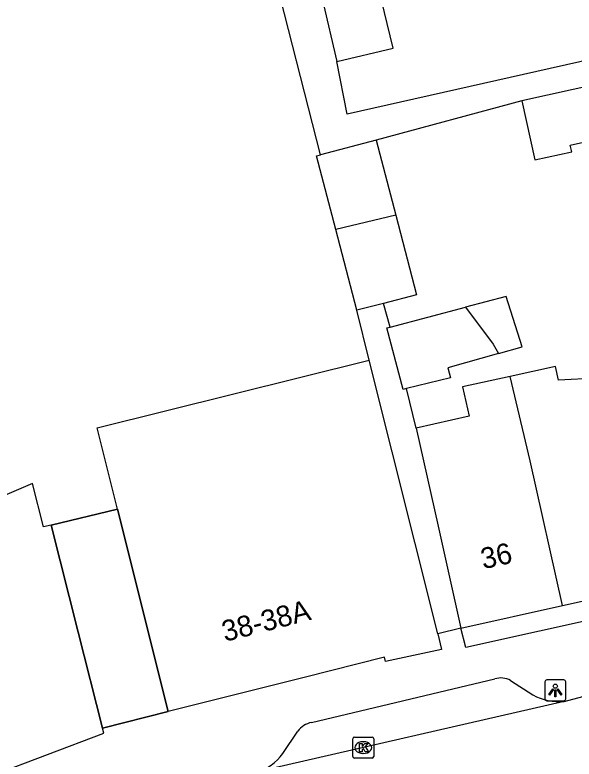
# Model space of a CAD drawing. Extents: x 160861 to 161308, y 384024 to 384878.
# Drawn here: x 160958.47 to 160985.24, y 384696.73 to 384732.38 of the extents above; entities that cross this region are included whole.
import ezdxf

# ---------------------------------------------------------------- set-up
doc = ezdxf.new("R2010")
doc.units = 0
for name, color, linetype in [('IMGEO_Kolk', 7, 'Continuous'), ('IMGEO_Lichtpunt', 7, 'Continuous'), ('IMGEO_Pand', 7, 'Continuous'), ('IMGEO_Pand_nummerreeks', 7, 'Continuous'), ('IMGEO_Pand_overbouw', 7, 'Continuous'), ('IMGEO_Rijbaan_lokaal_open', 7, 'Continuous'), ('IMGEO_Voetpad_open', 7, 'Continuous')]:
    doc.layers.add(name, color=color, linetype=linetype)

msp = doc.modelspace()

# ---------------------------------------------------------------- linework, layer by layer
at = {"layer": 'IMGEO_Kolk'}
for p, q in [((160974.647, 384696.86), (160974.647, 384697.712)), ((160974.722, 384697.786), (160975.574, 384697.786)), ((160975.648, 384697.712), (160975.648, 384696.86)), ((160975.135, 384697.566), (160975.16, 384697.566)), ((160975.158, 384697.006), (160975.133, 384697.006)), ((160975.574, 384696.786), (160974.722, 384696.786))]:
    msp.add_line(p, q, dxfattribs=at)
for points in [[(160974.647, 384696.86), (160974.647, 384697.712)], [(160974.722, 384697.786), (160975.574, 384697.786)], [(160975.648, 384697.712), (160975.648, 384696.86)], [(160974.968, 384697.486), (160975.091, 384697.486), (160975.091, 384697.335), (160975.221, 384697.486), (160975.385, 384697.486), (160975.239, 384697.335), (160975.392, 384697.086), (160975.24, 384697.086), (160975.155, 384697.25), (160975.091, 384697.183), (160975.091, 384697.086), (160974.968, 384697.086), (160974.968, 384697.486)], [(160975.574, 384696.786), (160974.722, 384696.786)]]:
    msp.add_lwpolyline(points, dxfattribs=at)
for centre, start, end in [((160974.724, 384697.71), 91.552, 178.448), ((160974.724, 384697.71), 91.552, 178.448), ((160975.572, 384697.71), 1.552, 88.448), ((160975.572, 384697.71), 1.552, 88.448), ((160974.724, 384696.862), 181.552, 268.448), ((160974.724, 384696.862), 181.552, 268.448), ((160975.572, 384696.862), 271.552, 358.448), ((160975.572, 384696.862), 271.552, 358.448)]:
    msp.add_arc(centre, 0.0765, start, end, dxfattribs=at)
for centre, major_axis, ratio, start_param, end_param in [((160975.134, 384697.286), (-0.387, 0.002), 0.722429, 4.712389, 7.853982), ((160975.159, 384697.286), (-0.39, 0.002), 0.717154, 1.570796, 4.712389)]:
    msp.add_ellipse(centre, major_axis=major_axis, ratio=ratio, start_param=start_param, end_param=end_param, dxfattribs=at)
at = {"layer": 'IMGEO_Lichtpunt'}
for p, q in [((160984.743, 384700.526), (160983.935, 384700.526)), ((160984.743, 384700.526), (160983.935, 384700.526)), ((160983.841, 384700.431), (160983.841, 384699.624)), ((160983.841, 384700.431), (160983.841, 384699.624)), ((160984.837, 384699.624), (160984.837, 384700.431)), ((160984.837, 384699.624), (160984.837, 384700.431)), ((160983.935, 384699.53), (160984.743, 384699.53)), ((160983.935, 384699.53), (160984.743, 384699.53))]:
    msp.add_line(p, q, dxfattribs=at)
for points in [[(160984.215, 384700.095), (160984.254, 384700.067), (160984.066, 384699.805), (160984.028, 384699.832), (160984.215, 384700.095)], [(160984.427, 384700.067), (160984.465, 384700.094), (160984.652, 384699.832), (160984.613, 384699.804), (160984.427, 384700.067)], [(160984.317, 384700.047), (160984.364, 384700.047), (160984.364, 384699.725), (160984.317, 384699.725), (160984.317, 384700.047)]]:
    msp.add_lwpolyline(points, dxfattribs=at)
msp.add_circle((160984.34, 384700.229), 0.0994, dxfattribs=at)
for centre, start, end in [((160983.935, 384700.431), 90, 180), ((160983.935, 384700.431), 90, 180), ((160984.743, 384700.431), 0, 90), ((160984.743, 384700.431), 0, 90), ((160983.935, 384699.624), 180, 270), ((160983.935, 384699.624), 180, 270), ((160984.743, 384699.624), 270, 0), ((160984.743, 384699.624), 270, 360)]:
    msp.add_arc(centre, 0.0946, start, end, dxfattribs=at)
at = {"layer": 'IMGEO_Pand'}
for points in [[(160973.888, 384730.142), (160976.574, 384730.783), (160975.879, 384733.694)], [(160973.188, 384733.076), (160973.888, 384730.142)], [(160995.703, 384731.143), (160990.823, 384730.057), (160989.029, 384729.658), (160982.734, 384728.258)], [(160982.734, 384728.258), (160983.361, 384725.436), (160985.122, 384725.827), (160985.052, 384726.144), (160988.896, 384727), (160989.382, 384724.816), (160989.67, 384724.855)], [(160975.765, 384726.38), (160973.093, 384725.682)], [(160975.765, 384726.38), (160976.702, 384722.794)], [(160973.834, 384722.103), (160972.911, 384725.634), (160973.093, 384725.682)], [(160976.702, 384722.794), (160973.834, 384722.103)], [(160976.702, 384722.794), (160977.699, 384718.976), (160976.116, 384718.562)], [(160974.846, 384718.23), (160973.834, 384722.103)], [(160981.616, 384716.158), (160982.749, 384716.48), (160981.991, 384718.891), (160980.044, 384718.377)], [(160976.116, 384718.562), (160974.846, 384718.23)], [(160976.44, 384717.427), (160980.044, 384718.377)], [(160980.044, 384718.377), (160981.367, 384716.612), (160981.616, 384716.158)], [(160977.217, 384714.479), (160977.052, 384714.438), (160976.276, 384717.384), (160976.44, 384717.427)], [(160981.616, 384716.158), (160979.191, 384715.469), (160979.324, 384715.002), (160977.217, 384714.479)], [(160963.386, 384708.712), (160962.416, 384712.593), (160975.435, 384715.845)], [(160978.712, 384702.734), (160975.435, 384715.845)], [(160986.323, 384714.974), (160984.491, 384714.881), (160984.343, 384715.546), (160982.183, 384715.066)], [(160982.183, 384715.066), (160979.897, 384714.557), (160980.209, 384713.153), (160977.685, 384712.592)], [(160984.675, 384704.086), (160983.133, 384711.017), (160982.183, 384715.066)], [(160977.685, 384712.592), (160978.732, 384707.886), (160979.817, 384703.005)], [(160984.675, 384704.086), (160989.534, 384705.167), (160988.046, 384711.86), (160989.006, 384711.905)], [(160960.205, 384707.945), (160959.838, 384707.852), (160959.313, 384709.933), (160955.281, 384708.212), (160955.527, 384707.559), (160952.723, 384706.502)], [(160963.386, 384708.712), (160965.811, 384699.01)], [(160962.66, 384698.215), (160961.498, 384702.822), (160960.205, 384707.945)], [(160979.817, 384703.005), (160984.675, 384704.086)], [(160978.712, 384702.734), (160978.898, 384701.99), (160976.207, 384701.405), (160976.168, 384701.622), (160972.317, 384700.651), (160965.811, 384699.01)], [(160954.629, 384694.918), (160962.721, 384697.973), (160962.66, 384698.215)]]:
    msp.add_lwpolyline(points, dxfattribs=at)
at = {"layer": 'IMGEO_Pand_overbouw'}
msp.add_lwpolyline([(160965.811, 384699.01), (160963.386, 384708.712), (160960.205, 384707.945), (160961.498, 384702.822), (160962.66, 384698.215)], close=True, dxfattribs=at)
at = {"layer": 'IMGEO_Rijbaan_lokaal_open'}
for points in [[(160960.205, 384707.945), (160963.386, 384708.712)], [(160984.769, 384699.502), (160987.198, 384700.153), (160988.789, 384701.138)], [(160984.769, 384699.502), (160970.01, 384696.102)], [(160965.811, 384699.01), (160962.66, 384698.215)]]:
    msp.add_lwpolyline(points, dxfattribs=at)
at = {"layer": 'IMGEO_Voetpad_open'}
for points in [[(160973.093, 384725.682), (160963.919, 384761.651)], [(160988.07, 384730.697), (160974.369, 384727.616), (160973.888, 384730.142)], [(160982.734, 384728.258), (160975.765, 384726.38)], [(160976.44, 384717.427), (160976.116, 384718.562)], [(160975.435, 384715.845), (160974.846, 384718.23)], [(160977.685, 384712.592), (160977.217, 384714.479)], [(160996.631, 384712.258), (160990.485, 384704.401), (160980.053, 384702.083), (160979.817, 384703.005)], [(160979.817, 384703.005), (160978.712, 384702.734)], [(160972.663, 384698.493), (160981.442, 384700.576)], [(160982.197, 384700.504), (160983.262, 384699.816)], [(160971.299, 384697.008), (160972.01, 384698.076)]]:
    msp.add_lwpolyline(points, dxfattribs=at)
for centre, radius, start, end in [((160981.734, 384699.641), 0.98, 61.7798, 107.3252), ((160984.496, 384701.967), 2.48, 240.1476, 276.3128), ((160972.945, 384697.331), 1.196, 103.6558, 141.4681), ((160969.389, 384698.355), 2.337, 285.4036, 324.8009)]:
    msp.add_arc(centre, radius, start, end, dxfattribs=at)

# ---------------------------------------------------------------- texts
at = {"layer": 'IMGEO_Pand_nummerreeks'}
for s, rotation, p in [('36', 12.5438, (160980.892, 384705.825)), ('38-38A', 14.404, (160968.525, 384702.347))]:
    msp.add_text(s, height=1, rotation=rotation, dxfattribs=at).set_placement(p)

doc.saveas('drawing.dxf')
